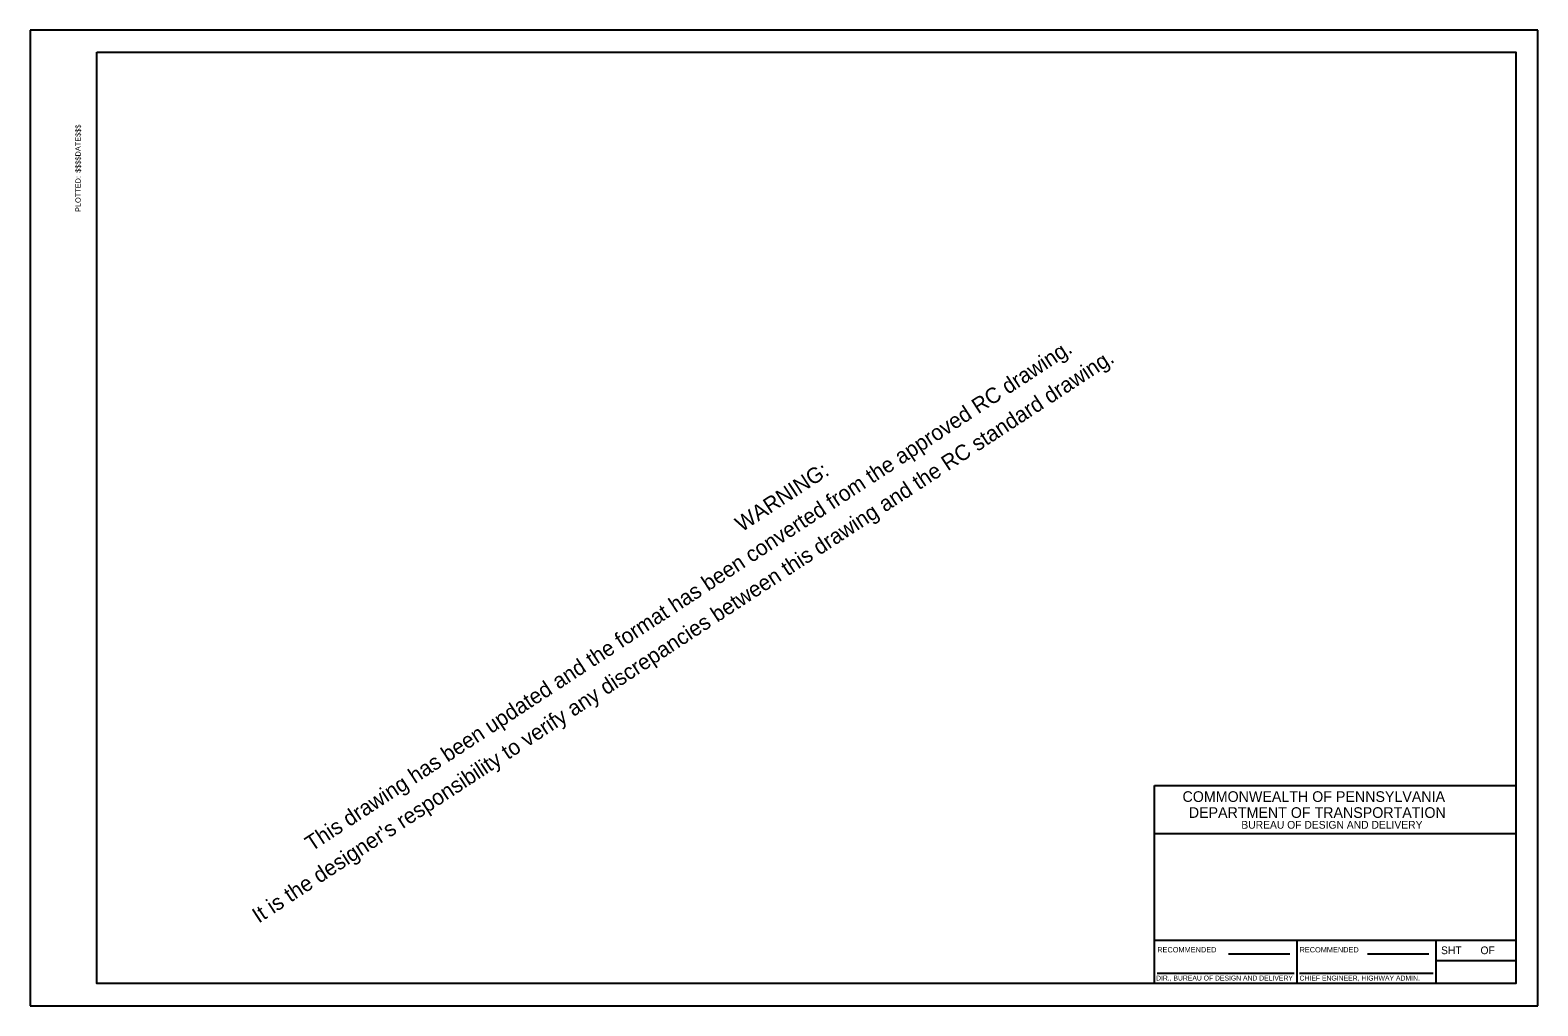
# Model space of a CAD drawing. Extents: x 0 to 2.83, y 0 to 1.83.
import ezdxf

# ---------------------------------------------------------------- set-up
doc = ezdxf.new("R2010")
doc.units = 0
for name, color, linetype in [('1', 7, 'Continuous'), ('C-PLAN-SHTS', 7, 'Continuous'), ('C-PLAN-SHTS-TEXT', 7, 'Continuous'), ('PLT-BNDY', 7, 'Continuous')]:
    doc.layers.add(name, color=color, linetype=linetype)

msp = doc.modelspace()

# ---------------------------------------------------------------- linework, layer by layer
at = {"layer": 'C-PLAN-SHTS'}
for p, q in [((2.1131, 0.0417), (2.1131, 0.414)), ((2.1131, 0.414), (2.7917, 0.414)), ((2.1131, 0.3241), (2.7917, 0.3241)), ((2.1131, 0.1235), (2.7917, 0.1235)), ((2.3805, 0.1235), (2.3805, 0.0417)), ((2.6417, 0.1235), (2.6417, 0.0417)), ((2.6417, 0.0852), (2.7917, 0.0852))]:
    msp.add_line(p, q, dxfattribs=at)
msp.add_lwpolyline([(0.125, 1.7917), (2.7917, 1.7917), (2.7917, 0.0417), (0.125, 0.0417)], close=True, dxfattribs=at)
at = {"layer": 'C-PLAN-SHTS-TEXT'}
for p, q in [((2.2522, 0.0975), (2.3672, 0.0975)), ((2.5134, 0.0975), (2.6283, 0.0975)), ((2.1181, 0.0616), (2.3755, 0.0616)), ((2.3855, 0.0616), (2.6365, 0.0616))]:
    msp.add_line(p, q, dxfattribs=at)
at = {"layer": 'PLT-BNDY'}
for p, q in [((2.8333, 1.8333), (0, 1.8333)), ((0, 1.8333), (0, 0)), ((2.8333, 0), (2.8333, 1.8333)), ((0, 0), (2.8333, 0))]:
    msp.add_line(p, q, dxfattribs=at)

# ---------------------------------------------------------------- texts
at = {"layer": '1'}
for s, height, p in [("It is the designer's responsibility to verify any discrepancies between this drawing and the RC standard drawing.", 0.0291667, (0.4295, 0.1543)), ('This drawing has been updated and the format has been converted from the approved RC drawing.', 0.029167, (0.529, 0.2893)), ('WARNING:', 0.02917, (1.3373, 0.8896))]:
    msp.add_text(s, height=height, rotation=33.2749, dxfattribs=at).set_placement(p)
at = {"layer": 'C-PLAN-SHTS-TEXT'}
for s, p in [('$$$$DATE$$$', (0.095, 1.5653)), ('PLOTTED:', (0.095, 1.4917))]:
    msp.add_text(s, height=0.01, rotation=90, dxfattribs=at).set_placement(p)
for s, height, p in [('COMMONWEALTH OF PENNSYLVANIA', 0.02, (2.1656, 0.3832)), ('DEPARTMENT OF TRANSPORTATION', 0.02, (2.1774, 0.3532)), ('BUREAU OF DESIGN AND DELIVERY', 0.0145, (2.2761, 0.3329)), ('RECOMMENDED', 0.01, (2.1181, 0.1004)), ('RECOMMENDED', 0.01, (2.3855, 0.1004)), ('SHT ', 0.0145, (2.6514, 0.0971)), ('   OF', 0.0145, (2.7094, 0.0971)), ('DIR., BUREAU OF DESIGN AND DELIVERY', 0.009255, (2.1159, 0.0476)), ('CHIEF ENGINEER, HIGHWAY ADMIN.', 0.0093, (2.3855, 0.0475))]:
    msp.add_text(s, height=height, dxfattribs=at).set_placement(p)

doc.saveas('drawing.dxf')
